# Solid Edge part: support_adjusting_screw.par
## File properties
Accuracy: 0.99
Title: Support adjusting screw
Author: Robert a Rhodes jr
Template: Normal.par
Last saved by: CADCIM
Revision: 10
Application: Solid Edge
Material: aluminum
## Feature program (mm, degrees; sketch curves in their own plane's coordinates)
sketch for "unnamed Protrusion 1" plane through (0, 0, 0) normal (0, -1, 0) x-axis (1, 0, 0)
  circle centre (0, 0) radius 38.1
extrude "unnamed Protrusion 1" add finite 584.2 along +normal
sketch for "ExtrudedCutout_1" plane through (0, -521.208, 0) normal (0, -1, 0) x-axis (1, 0, 0)
extrude "ExtrudedCutout_1" cut finite 76.2 along +normal  Plane_Distance = 62.992 mm
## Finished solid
Body 1: solid body, 5 faces, 4 edges, 0 vertices.
  Faces by surface: plane 3, cylinder 2
  Edges by curve: circle 4
Bounding box of the edges (mm): 76.200 x 584.200 x 76.200, from (-38.1, -584.2, -38.1) to (38.1, 0, 38.1).
Cylindrical faces by radius (mm): R25.4 x1, R38.1 x1
Planar faces by outward normal: +y 1, -y 2
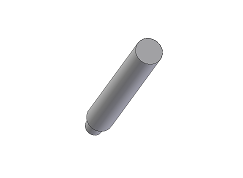
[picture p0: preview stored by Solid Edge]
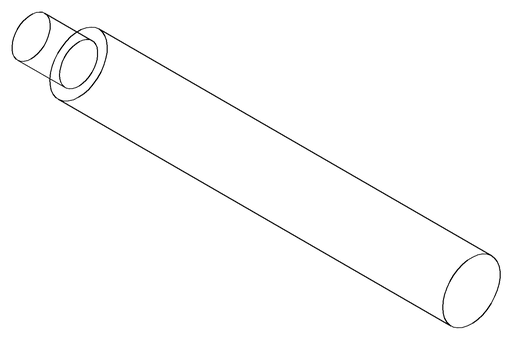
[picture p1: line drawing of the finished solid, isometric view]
